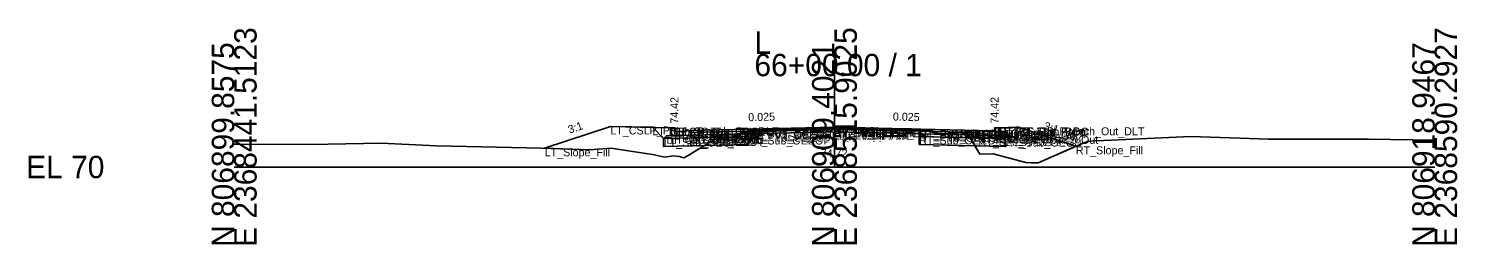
# Model space of a CAD drawing. Extents: x -26 to 8153, y -10 to 9520.
# Drawn here: x 5974.3 to 6152.8, y 6490.3 to 6517.3 of the extents above; entities that cross this region are included whole.
import ezdxf

# ---------------------------------------------------------------- set-up
doc = ezdxf.new("R2010")
doc.units = 0
for name, color, linetype in [('Exist CMT Pavement', 7, 'Continuous'), ('Exist Cross Section Cell', 7, 'Continuous'), ('Exist XS Center Line Elevation Label', 7, 'Continuous'), ('Exist XS Ground Line', 7, 'Continuous'), ('Prop CMT Conc Surface', 7, 'Continuous'), ('Prop CMT Concrete Structures', 7, 'Continuous'), ('Prop CMT Pvmt Course 1', 7, 'Continuous'), ('Prop CMT Pvmt Course 1 CG', 7, 'Continuous'), ('Prop CMT Pvmt Course 1 Wedge', 7, 'Continuous'), ('Prop CMT Pvmt Course 2', 7, 'Continuous'), ('Prop CMT Pvmt Course 2 Wedge', 7, 'Continuous'), ('Prop CMT Pvmt Course 3', 7, 'Continuous'), ('Prop CMT Pvmt Course 3 Wedge', 7, 'Continuous'), ('Prop CMT Pvmt Surface', 7, 'Continuous'), ('Prop CMT Pvmt Wedge Surface 1', 7, 'Continuous'), ('Prop CMT Pvmt Wedge Surface 2', 7, 'Continuous'), ('Prop CMT Pvmt Wedge Surface 3', 7, 'Continuous'), ('Prop CMT Shallow Undercut', 7, 'Continuous'), ('Prop CMT Shallow Undercut Boundary', 7, 'Continuous'), ('Prop CMT Slope Grass', 7, 'Continuous'), ('Prop CMT Subgrade Earthwork', 7, 'Continuous'), ('Prop XS Earthwork Shape', 7, 'Continuous'), ('Prop XS Hydro Elevations', 7, 'Continuous'), ('Prop XS SE Text', 7, 'Continuous'), ('Prop XS Side Slope Text', 7, 'Continuous'), ('Prop XS Subgrade Earthwork', 7, 'Continuous'), ('Scratch_Level_2', 7, 'Continuous'), ('Scratch_Level_6', 7, 'Continuous')]:
    doc.layers.add(name, color=color, linetype=linetype)

msp = doc.modelspace()

# ---------------------------------------------------------------- linework, layer by layer
at = {"layer": 'Exist CMT Pavement'}
for p, q in [((6064.32, 6504.34), (6071.05, 6504.61)), ((6071.05, 6504.61), (6074.67, 6504.72)), ((6074.67, 6504.72), (6075, 6504.72)), ((6075, 6504.72), (6078.14, 6504.68)), ((6078.14, 6504.68), (6085.6, 6504.65))]:
    msp.add_line(p, q, dxfattribs=at)
at = {"layer": 'Exist Cross Section Cell'}
for p, q in [((6075, 6500), (6075, 6514.16)), ((6000, 6500), (6075, 6500)), ((6075, 6500), (6150, 6500))]:
    msp.add_line(p, q, dxfattribs=at)
at = {"layer": 'Exist XS Ground Line'}
for p, q in [((6060.61, 6503.82), (6061.56, 6504.13)), ((6061.56, 6504.13), (6062.39, 6504.07)), ((6062.39, 6504.07), (6062.82, 6504.05)), ((6062.82, 6504.05), (6064.32, 6504.34)), ((6064.32, 6504.34), (6071.05, 6504.61)), ((6071.05, 6504.61), (6074.67, 6504.72)), ((6074.67, 6504.72), (6075, 6504.72)), ((6075, 6504.72), (6078.14, 6504.68)), ((6078.14, 6504.68), (6085.6, 6504.65)), ((6085.6, 6504.65), (6088.34, 6504.16)), ((6088.34, 6504.16), (6090.12, 6504.24)), ((6090.12, 6504.24), (6090.95, 6504.34)), ((6090.95, 6504.34), (6091.67, 6504.17)), ((6091.67, 6504.17), (6093.16, 6501.6)), ((6000, 6502.86), (6000.68, 6502.86)), ((6000.68, 6502.86), (6009.52, 6502.82)), ((6009.52, 6502.82), (6018.36, 6502.99)), ((6018.36, 6502.99), (6025.28, 6502.63)), ((6025.28, 6502.63), (6038.41, 6502.35)), ((6038.41, 6502.35), (6044.42, 6502.16)), ((6044.42, 6502.16), (6047.09, 6502.37)), ((6047.09, 6502.37), (6051.67, 6501.66)), ((6056.71, 6501.42), (6060.61, 6503.82)), ((6102.06, 6501.24), (6106, 6502.95)), ((6106, 6502.95), (6106.61, 6503.2)), ((6106.61, 6503.2), (6107.33, 6503.26)), ((6107.33, 6503.26), (6108.66, 6503.32)), ((6108.66, 6503.32), (6119.47, 6503.82)), ((6119.47, 6503.82), (6124.44, 6503.64)), ((6124.44, 6503.64), (6129.23, 6503.48)), ((6129.23, 6503.48), (6136.85, 6503.5)), ((6136.85, 6503.5), (6139.64, 6503.48)), ((6139.64, 6503.48), (6141.71, 6503.47)), ((6141.71, 6503.47), (6150, 6503.35)), ((6051.67, 6501.66), (6052.29, 6501.55)), ((6052.29, 6501.55), (6053.78, 6501.22)), ((6053.78, 6501.22), (6054.88, 6501.38)), ((6054.88, 6501.38), (6055.61, 6501.33)), ((6055.61, 6501.33), (6056.17, 6501.14)), ((6056.17, 6501.14), (6056.71, 6501.42)), ((6093.16, 6501.6), (6094.84, 6501.65)), ((6094.84, 6501.65), (6098.91, 6500.58)), ((6098.91, 6500.58), (6099.57, 6500.53)), ((6099.57, 6500.53), (6100.44, 6500.51)), ((6100.44, 6500.51), (6102.06, 6501.24))]:
    msp.add_line(p, q, dxfattribs=at)
at = {"layer": 'Prop CMT Conc Surface'}
for points in [[(6055, 6504.42), (6055, 6504.92), (6054.5, 6504.92)], [(6057, 6504.55), (6055, 6504.42)], [(6093, 6504.55), (6095, 6504.42)], [(6095, 6504.42), (6095, 6504.92), (6095.5, 6504.92)]]:
    msp.add_lwpolyline(points, dxfattribs=at)
at = {"layer": 'Prop CMT Concrete Structures'}
for points in [[(6057, 6504.55), (6055, 6504.42), (6055, 6504.92), (6054.5, 6504.92)], [(6054.5, 6504.92), (6054.5, 6503.91), (6057, 6503.97)], [(6057, 6503.97), (6057, 6504.55)], [(6093, 6504.55), (6095, 6504.42), (6095, 6504.92), (6095.5, 6504.92)], [(6095.5, 6504.92), (6095.5, 6503.91), (6093, 6503.97)], [(6093, 6503.97), (6093, 6504.55)]]:
    msp.add_lwpolyline(points, dxfattribs=at)
at = {"layer": 'Prop CMT Pvmt Course 1'}
for points in [[(6075, 6505), (6057, 6504.55)], [(6057, 6504.55), (6057, 6504.3)], [(6057, 6504.3), (6064.32, 6504.49)], [(6064.32, 6504.61), (6075, 6504.88)], [(6064.32, 6504.49), (6064.32, 6504.61)], [(6075, 6504.75), (6075, 6505)], [(6075, 6505), (6093, 6504.55)], [(6075, 6504.75), (6075, 6505)], [(6075, 6504.88), (6075, 6504.75), (6075, 6504.75)], [(6085.6, 6504.61), (6075, 6504.88)], [(6075, 6504.88), (6075, 6504.75), (6075, 6504.75)], [(6085.6, 6504.49), (6085.6, 6504.61)], [(6093, 6504.3), (6085.6, 6504.49)], [(6093, 6504.55), (6093, 6504.3)]]:
    msp.add_lwpolyline(points, dxfattribs=at)
at = {"layer": 'Prop CMT Pvmt Course 1 CG'}
for points in [[(6057, 6503.97), (6054, 6503.9), (6053.66, 6503.56)], [(6057, 6503.64), (6057, 6503.97)], [(6093, 6503.97), (6096, 6503.9), (6096.34, 6503.56)], [(6093, 6503.64), (6093, 6503.97)], [(6053.66, 6503.56), (6057, 6503.64)], [(6096.34, 6503.56), (6093, 6503.64)]]:
    msp.add_lwpolyline(points, dxfattribs=at)
at = {"layer": 'Prop CMT Pvmt Course 1 Wedge'}
for points in [[(6075, 6504.88), (6064.32, 6504.61)], [(6075, 6504.88), (6085.6, 6504.61)]]:
    msp.add_lwpolyline(points, dxfattribs=at)
at = {"layer": 'Prop CMT Pvmt Course 2'}
for points in [[(6064.32, 6504.49), (6057, 6504.3)], [(6057, 6504.3), (6057, 6503.97)], [(6057, 6503.97), (6064.32, 6504.16)], [(6064.32, 6504.16), (6064.32, 6504.49)], [(6085.6, 6504.16), (6085.6, 6504.49)], [(6085.6, 6504.49), (6093, 6504.3)], [(6093, 6503.97), (6085.6, 6504.16)], [(6093, 6504.3), (6093, 6503.97)]]:
    msp.add_lwpolyline(points, dxfattribs=at)
at = {"layer": 'Prop CMT Pvmt Course 2 Wedge'}
for points in [[(6075, 6504.75), (6064.32, 6504.49)], [(6075, 6504.75), (6085.6, 6504.49)]]:
    msp.add_lwpolyline(points, dxfattribs=at)
at = {"layer": 'Prop CMT Pvmt Course 3'}
for points in [[(6064.32, 6504.16), (6057, 6503.97)], [(6057, 6503.97), (6057, 6503.64)], [(6064.32, 6503.82), (6064.32, 6504.16)], [(6085.6, 6504.16), (6093, 6503.97)], [(6085.6, 6503.83), (6085.6, 6504.16)], [(6093, 6503.97), (6093, 6503.64)], [(6057, 6503.64), (6064.32, 6503.82)], [(6093, 6503.64), (6085.6, 6503.83)]]:
    msp.add_lwpolyline(points, dxfattribs=at)
at = {"layer": 'Prop CMT Pvmt Course 3 Wedge'}
for points in [[(6075, 6504.42), (6064.32, 6504.16)], [(6075, 6504.42), (6085.6, 6504.16)]]:
    msp.add_lwpolyline(points, dxfattribs=at)
at = {"layer": 'Prop CMT Pvmt Surface'}
for points in [[(6075, 6505), (6057, 6504.55)], [(6075, 6505), (6093, 6504.55)]]:
    msp.add_lwpolyline(points, dxfattribs=at)
at = {"layer": 'Prop CMT Pvmt Wedge Surface 1'}
for points in [[(6057, 6504.3), (6057, 6504.55)], [(6064.32, 6504.49), (6057, 6504.3)], [(6075, 6504.88), (6064.32, 6504.61)], [(6064.32, 6504.61), (6064.32, 6504.49)], [(6075, 6504.88), (6085.6, 6504.61)], [(6085.6, 6504.61), (6085.6, 6504.49)], [(6085.6, 6504.49), (6093, 6504.3)], [(6093, 6504.3), (6093, 6504.55)]]:
    msp.add_lwpolyline(points, dxfattribs=at)
at = {"layer": 'Prop CMT Pvmt Wedge Surface 2'}
for points in [[(6075, 6504.75), (6057, 6504.3)], [(6057, 6504.3), (6057, 6504.55)], [(6075, 6504.75), (6093, 6504.3)], [(6093, 6504.3), (6093, 6504.55)]]:
    msp.add_lwpolyline(points, dxfattribs=at)
at = {"layer": 'Prop CMT Pvmt Wedge Surface 3'}
for points in [[(6057, 6503.97), (6057, 6504.55)], [(6075, 6504.42), (6057, 6503.97)], [(6075, 6504.42), (6093, 6503.97)], [(6093, 6503.97), (6093, 6504.55)]]:
    msp.add_lwpolyline(points, dxfattribs=at)
at = {"layer": 'Prop CMT Shallow Undercut'}
for points in [[(6064.32, 6503.82), (6064.32, 6502.82), (6058.77, 6502.68), (6060.46, 6503.73)], [(6085.6, 6502.83), (6092.55, 6502.65), (6091.96, 6503.67), (6085.6, 6503.83)]]:
    msp.add_lwpolyline(points, close=True, dxfattribs=at)
at = {"layer": 'Prop CMT Shallow Undercut Boundary'}
for p, q in [((6053.66, 6503.56), (6053.66, 6502.56)), ((6053.66, 6502.56), (6064.32, 6502.82)), ((6064.32, 6503.82), (6064.32, 6502.82)), ((6085.6, 6503.83), (6085.6, 6502.83)), ((6085.6, 6502.83), (6096.34, 6502.56)), ((6096.34, 6503.56), (6096.34, 6502.56))]:
    msp.add_line(p, q, dxfattribs=at)
at = {"layer": 'Prop CMT Slope Grass'}
for points in [[(6054.5, 6504.92), (6047, 6505.07), (6038.79, 6502.34)], [(6095.5, 6504.92), (6098, 6504.97), (6105.16, 6502.59)]]:
    msp.add_lwpolyline(points, dxfattribs=at)
at = {"layer": 'Prop CMT Subgrade Earthwork'}
for points in [[(6057, 6503.64), (6053.66, 6503.56), (6052.25, 6504.97)], [(6064.32, 6503.82), (6064.34, 6504.34)], [(6085.6, 6503.83), (6085.58, 6504.65)], [(6093, 6503.64), (6096.34, 6503.56), (6097.75, 6504.97)], [(6064.32, 6503.82), (6057, 6503.64)], [(6085.6, 6503.83), (6093, 6503.64)]]:
    msp.add_lwpolyline(points, dxfattribs=at)
at = {"layer": 'Prop XS Earthwork Shape'}
for points in [[(6047.09, 6502.37), (6051.67, 6501.66), (6052.29, 6501.55), (6053.78, 6501.22), (6054.88, 6501.38), (6055.61, 6501.33), (6056.17, 6501.14), (6056.71, 6501.42), (6058.77, 6502.68), (6053.66, 6502.56), (6053.66, 6503.56), (6052.25, 6504.97), (6047, 6505.07), (6038.79, 6502.34), (6044.42, 6502.16)], [(6061.56, 6504.13), (6062.39, 6504.07), (6062.82, 6504.05), (6064.32, 6504.34), (6064.34, 6504.34), (6064.32, 6503.82), (6060.46, 6503.73), (6060.61, 6503.82)], [(6090.95, 6504.34), (6091.67, 6504.17), (6091.96, 6503.67), (6085.6, 6503.83), (6085.58, 6504.65), (6085.6, 6504.65), (6088.34, 6504.16), (6090.12, 6504.24)], [(6100.44, 6500.51), (6102.06, 6501.24), (6105.16, 6502.59), (6098, 6504.97), (6097.75, 6504.97), (6096.34, 6503.56), (6096.34, 6502.56), (6092.55, 6502.65), (6093.16, 6501.6), (6094.84, 6501.65), (6098.91, 6500.58), (6099.57, 6500.53)], [(6058.77, 6502.68), (6060.46, 6503.73), (6057, 6503.64), (6053.66, 6503.56), (6053.66, 6502.56)], [(6058.77, 6502.68), (6060.46, 6503.73), (6064.32, 6503.82), (6064.32, 6502.82)], [(6085.6, 6502.83), (6092.55, 6502.65), (6091.96, 6503.67), (6085.6, 6503.83)], [(6091.96, 6503.67), (6092.55, 6502.65), (6096.34, 6502.56), (6096.34, 6503.56), (6093, 6503.64)]]:
    msp.add_lwpolyline(points, close=True, dxfattribs=at)
at = {"layer": 'Prop XS Subgrade Earthwork'}
for p, q in [((6053.66, 6503.56), (6064.32, 6503.82)), ((6085.6, 6503.83), (6096.34, 6503.56))]:
    msp.add_line(p, q, dxfattribs=at)
at = {"layer": 'Scratch_Level_6'}
for points in [[(6064.32, 6503.82), (6064.32, 6502.82), (6058.77, 6502.68), (6060.46, 6503.73)], [(6085.6, 6502.83), (6092.55, 6502.65), (6091.96, 6503.67), (6085.6, 6503.83)]]:
    msp.add_lwpolyline(points, close=True, dxfattribs=at)

# ---------------------------------------------------------------- texts
at = {"layer": 'Exist Cross Section Cell'}
for s, p in [('E 2368441.5123', (6002.8, 6490)), ('E 2368515.9025', (6077.8, 6490)), ('E 2368590.2927', (6152.8, 6490)), ('N 806899.8575', (6000, 6490)), ('N 806909.4021', (6075, 6490)), ('N 806918.9467', (6150, 6490))]:
    msp.add_text(s, height=2.8, rotation=90, dxfattribs=at).set_placement(p)
for s, p in [('L', (6065, 6514.16)), ('66+00.00 / 1', (6065, 6511.36)), ('EL 70', (5974, 6498.6))]:
    msp.add_text(s, height=2.8, dxfattribs=at).set_placement(p)
at = {"layer": 'Exist XS Center Line Elevation Label'}
msp.add_text('74.72', height=1, dxfattribs=at).set_placement((6073.29, 6501.22))
at = {"layer": 'Prop XS Hydro Elevations'}
for p in [(6055.5, 6505.42), (6095.5, 6505.42)]:
    msp.add_text('74.42', height=1, rotation=90, dxfattribs=at).set_placement(p)
at = {"layer": 'Prop XS SE Text'}
for rotation, p in [(1.4321, (6064.24, 6505.73)), (358.5679, (6082.29, 6505.82))]:
    msp.add_text('0.025', height=1, rotation=rotation, dxfattribs=at).set_placement(p)
at = {"layer": 'Prop XS Side Slope Text'}
for rotation, p in [(18.4349, (6041.9, 6504.17)), (341.5651, (6101.07, 6504.74))]:
    msp.add_text('3:1', height=1, rotation=rotation, dxfattribs=at).set_placement(p)
at = {"layer": 'Scratch_Level_2'}
for s, p in [('LT_CSLP_Pnt', (6047, 6504.07)), ('LT_Sub_Trench_Out_DLT', (6052.25, 6503.97)), ('LT_CG1_Shelf_Out', (6054, 6502.9)), ('LT_CG_Top_BOC', (6054.5, 6503.92)), ('LT_CG_Top_Face', (6055, 6503.92)), ('LT_CG_Top_Gut', (6055, 6503.42)), ('LT_PV1_OEOT', (6057, 6503.55)), ('LT_PV2_OEOT', (6057, 6503.3)), ('LT_PV3_OEOT', (6057, 6502.97)), ('LT_CG_Bot_IE', (6057, 6502.97)), ('LT_PV1_OEEOP', (6064.32, 6503.61)), ('LT_PV2_OEEOP', (6064.32, 6503.49)), ('LT_PV_OEEOP_EG', (6064.32, 6503.34)), ('LT_PV3_OEEOP', (6064.32, 6503.16)), ('LT_PV_Sub_Tie_Out', (6064.34, 6503.34)), ('PV1_PGL', (6075, 6504)), ('RT_PV1_IEEOP', (6075, 6503.88)), ('LT_PV1_IEEOP', (6075, 6503.88)), ('RT_PV2_IEEOP', (6075, 6503.75)), ('LT_PV2_IEEOP', (6075, 6503.75)), ('PV2_PGL', (6075, 6503.75)), ('RT_PV_IEEOP_EG', (6075, 6503.72)), ('LT_PV_IEEOP_EG', (6075, 6503.72)), ('RT_PV3_IEEOP', (6075, 6503.42)), ('LT_PV3_IEEOP', (6075, 6503.42)), ('RT_PV_Sub_Tie_Out', (6085.58, 6503.65)), ('RT_PV_OEEOP_EG', (6085.6, 6503.65)), ('RT_PV1_OEEOP', (6085.6, 6503.61)), ('RT_PV2_OEEOP', (6085.6, 6503.49)), ('RT_PV3_OEEOP', (6085.6, 6503.16)), ('RT_PV1_OEOT', (6093, 6503.55)), ('RT_PV2_OEOT', (6093, 6503.3)), ('RT_PV3_OEOT', (6093, 6502.97)), ('RT_CG_Bot_IE', (6093, 6502.97)), ('RT_CG_Top_Face', (6095, 6503.92)), ('RT_CG_Top_Gut', (6095, 6503.42)), ('RT_CG_Top_BOC', (6095.5, 6503.92)), ('RT_CG1_Shelf_Out', (6096, 6502.9)), ('RT_Sub_Trench_Out_DLT', (6097.75, 6503.97)), ('RT_CSLP_Pnt', (6098, 6503.97)), ('LT_Slope_Fill', (6038.79, 6501.34)), ('LT_Sub_OEOP', (6053.66, 6502.56)), ('LT_CG_Bot_BOC', (6054.5, 6502.91)), ('LT_Sub_OEOT', (6057, 6502.64)), ('LT_Sub_OEEOP', (6064.32, 6502.82)), ('RT_Sub_OEEOP', (6085.6, 6502.83)), ('RT_Sub_OEOT', (6093, 6502.64)), ('RT_CG_Bot_BOC', (6095.5, 6502.91)), ('RT_Sub_OEOP', (6096.34, 6502.56)), ('RT_Slope_Fill', (6105.16, 6501.59))]:
    msp.add_text(s, height=1, dxfattribs=at).set_placement(p)

doc.saveas('drawing.dxf')
